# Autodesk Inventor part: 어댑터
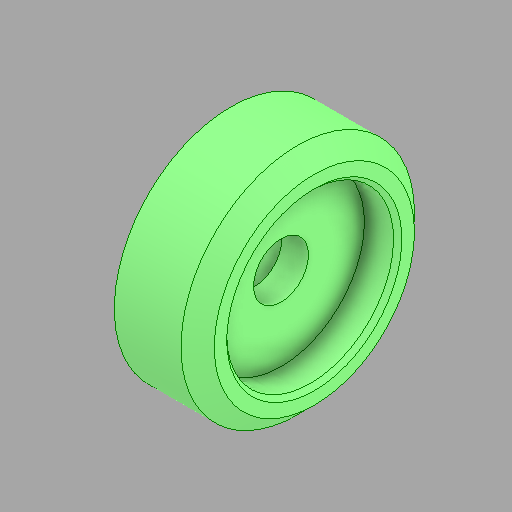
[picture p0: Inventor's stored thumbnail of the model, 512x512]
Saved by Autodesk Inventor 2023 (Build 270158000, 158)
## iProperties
Created: 2025-09
Part Number: 어댑터
Material: 강철, 탄소
Document SubType Name: Modeling
Designer: home
Density: 7.85 g/cm^3
Appearance: 기본값
Author: jhkim
Sending System: Autodesk Inventor 2026
Preprocessor: ST-DEVELOPER v20.1
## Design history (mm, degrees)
feature "솔리드1"
node "솔리드2"
